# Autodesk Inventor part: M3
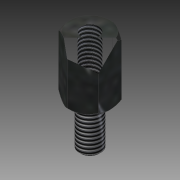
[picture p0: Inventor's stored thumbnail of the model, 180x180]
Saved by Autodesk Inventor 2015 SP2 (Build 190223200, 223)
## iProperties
Created: 2012-08
Part Number: M3
Material: Stahl
Document SubType Name: Modeling
Designer: rYan
Density: 7.85 g/cm^3
Mass: 1.74537 g
Surface Area: 3.04272 cm^2
Volume: 0.22234 cm^3
Appearance: Platte
Author: rYan
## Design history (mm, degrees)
derived "Abstandsbolzen Typ B.ipt"
feature "Volumenkörper1::Abstandsbolzen Typ B.ipt"
tag "Bezeichnung1"
node "Volumenkörper1"
other parameters: "SW" = 5.5, "L" = 8, "d2" = 0, "l_" = 6.5, "d9" = 118 deg, "GA_" = 3, "A_" = 6, "d13" = 0, "d17" = 0.25, "d20" = 45 deg
